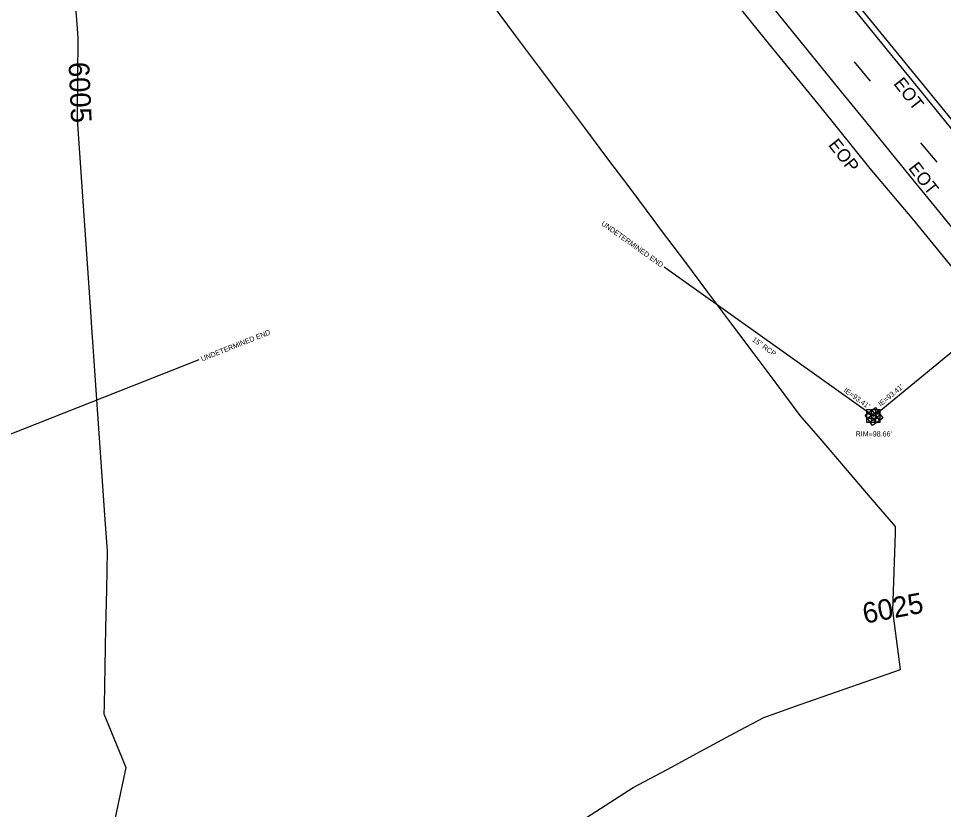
# Model space of a CAD drawing. Extents: x 2132221 to 2141942, y 535736 to 547298.
# Drawn here: x 2137234.9 to 2137595.1, y 540935.8 to 541243.7 of the extents above; entities that cross this region are included whole.
import ezdxf

# ---------------------------------------------------------------- set-up
doc = ezdxf.new("R2010")
doc.units = 0
for name, color, linetype in [('RD_EX_DR_Inlet', 7, 'Continuous'), ('RD_EX_DR_Inlet_txCode', 7, 'Continuous'), ('RD_EX_DR_Pipe', 7, 'Continuous'), ('RD_EX_DR_Pipe_txCode', 7, 'Continuous'), ('RD_EX_Misc', 7, 'Continuous'), ('RD_EX_Misc_txCode', 7, 'Continuous'), ('RD_EX_Road', 7, 'Continuous'), ('RD_EX_Road_txCode', 7, 'Continuous'), ('RD_EX_VEG', 7, 'Continuous'), ('RD_HC_TX_Sta50', 7, 'Continuous')]:
    doc.layers.add(name, color=color, linetype=linetype)

msp = doc.modelspace()

# ---------------------------------------------------------------- linework, layer by layer
at = {"layer": 'RD_EX_DR_Inlet'}
for p, q in [((2137569.6, 541090.81), (2137565.52, 541087.91)), ((2137566.95, 541091.43), (2137566.95, 541086.43)), ((2137567.23, 541091.21), (2137570.13, 541087.14)), ((2137568.65, 541091.43), (2137568.65, 541086.43)), ((2137565.25, 541089.73), (2137570.25, 541089.73)), ((2137565.25, 541088.03), (2137570.25, 541088.03)), ((2137565.84, 541090.23), (2137568.74, 541086.15)), ((2137570.58, 541089.43), (2137566.51, 541086.53))]:
    msp.add_line(p, q, dxfattribs=at)
for points in [[(2137564.54, 541089.3), (2137568.61, 541092.2), (2137571.51, 541088.12), (2137567.44, 541085.22)], [(2137565.25, 541086.43), (2137565.25, 541091.43), (2137570.25, 541091.43), (2137570.25, 541086.43)]]:
    msp.add_lwpolyline(points, close=True, dxfattribs=at)
at = {"layer": 'RD_EX_DR_Pipe'}
for p, q in [((2137567.79, 541088.87), (2137663.53, 541167.56)), ((2137567.79, 541088.87), (2137486.33, 541146.92)), ((2137103.49, 541031.08), (2137305.29, 541110.96))]:
    msp.add_line(p, q, dxfattribs=at)
at = {"layer": 'RD_EX_Misc'}
for p, q in [((2137560.26, 541226.82), (2137566.56, 541219.29)), ((2137586.15, 541195.28), (2137592.45, 541187.76))]:
    msp.add_line(p, q, dxfattribs=at)
for points in [[(2137554.23, 541254.65), (2137563.7, 541243.01), (2137573.16, 541231.38), (2137582.62, 541219.74), (2137592.09, 541208.1), (2137601.55, 541196.47)], [(2137526.86, 541250.09), (2137536.32, 541238.45), (2137545.78, 541226.81), (2137555.25, 541215.18), (2137564.71, 541203.54), (2137574.18, 541191.9), (2137583.64, 541180.26), (2137593.1, 541168.63), (2137602.57, 541156.99)]]:
    msp.add_lwpolyline(points, dxfattribs=at)
at = {"layer": 'RD_EX_Road'}
for points in [[(2137129.75, 541780.57), (2137152.42, 541752.13), (2137176.05, 541723.37), (2137199.18, 541694.95), (2137221.19, 541667.61), (2137243.48, 541640.3), (2137267.28, 541610.96), (2137291.46, 541581.15), (2137312.24, 541555.53), (2137336.72, 541525.3), (2137359.73, 541497.32), (2137378.4, 541474.19), (2137407.74, 541438.19), (2137425.75, 541416.17), (2137446.57, 541390.46), (2137472.54, 541358.27), (2137492.89, 541333.37), (2137514.29, 541307.17), (2137539.52, 541276.53), (2137564.39, 541245.78), (2137586.4, 541218.72), (2137608.31, 541191.93)], [(2137503.28, 541263.26), (2137525.6, 541235.47), (2137547.28, 541208.98), (2137566.43, 541185.33), (2137582.75, 541165.94)], [(2137582.75, 541165.94), (2137604.28, 541139.57), (2137634.31, 541102.54), (2137665.62, 541063.89), (2137693.36, 541029.71), (2137721.58, 540994.92), (2137743.66, 540967.84), (2137762.64, 540943.97), (2137785.25, 540916.82), (2137799.37, 540899.43), (2137792.62, 540897.56), (2137777.51, 540904.78)]]:
    msp.add_lwpolyline(points, dxfattribs=at)
at = {"layer": 'RD_EX_VEG'}
for points in [[(2137256.47, 541256.45), (2137257.64, 541241.49), (2137258.06, 541236.1), (2137257.94, 541221.1), (2137257.82, 541206.1), (2137257.8, 541204.34), (2137258.84, 541189.38), (2137259.88, 541174.41), (2137260.91, 541159.45), (2137261.95, 541144.48), (2137262.99, 541129.52), (2137263.41, 541123.37), (2137264.45, 541108.41), (2137265.49, 541093.44), (2137266.52, 541078.48), (2137267.56, 541063.52), (2137268.6, 541048.55), (2137269.44, 541036.42), (2137269.15, 541021.42), (2137268.86, 541006.42), (2137268.57, 540991.43), (2137268.29, 540976.43), (2137268.22, 540972.93), (2137273.91, 540959.05), (2137276.77, 540952.08), (2137273.63, 540937.42), (2137270.48, 540922.75)], [(2137454.33, 540931.5), (2137466.95, 540939.6), (2137474.23, 540944.27), (2137487.45, 540951.36), (2137500.67, 540958.45), (2137513.88, 540965.54), (2137525.16, 540971.59), (2137539.31, 540976.57), (2137553.46, 540981.55), (2137567.61, 540986.53), (2137578.32, 540990.3), (2137576.41, 541005.18), (2137575.38, 541013.28), (2137575.87, 541028.27), (2137576.36, 541043.26), (2137576.45, 541045.88), (2137566.68, 541057.26), (2137556.92, 541068.65), (2137547.15, 541080.04), (2137539.32, 541089.17), (2137530.32, 541101.17), (2137521.33, 541113.17), (2137512.33, 541125.17), (2137503.33, 541137.18), (2137494.33, 541149.18), (2137485.34, 541161.18), (2137482.43, 541165.06), (2137473.43, 541177.06), (2137464.43, 541189.06), (2137455.44, 541201.06), (2137446.44, 541213.07), (2137437.44, 541225.07), (2137428.45, 541237.07), (2137419.45, 541249.07)]]:
    msp.add_lwpolyline(points, dxfattribs=at)

# ---------------------------------------------------------------- texts
at = {"layer": 'RD_EX_DR_Inlet_txCode'}
for s, rotation, p in [('UNDETERMINED END', 324.5239, (2137461.63, 541163.4)), ('UNDETERMINED END', 21.5951, (2137306.43, 541110.15)), ("IE=93.41'", 324.5239, (2137556.03, 541098.48)), ("IE=93.41'", 39.4173, (2137570.63, 541092.5))]:
    msp.add_text(s, height=2, rotation=rotation, dxfattribs=at).set_placement(p)
msp.add_text("RIM=98.66'", height=2, dxfattribs=at).set_placement((2137560.88, 541080.95))
at = {"layer": 'RD_EX_DR_Pipe_txCode'}
msp.add_text('15" RCP', height=2, rotation=324.5239, dxfattribs=at).set_placement((2137520.38, 541118.22))
at = {"layer": 'RD_EX_Misc_txCode'}
for p in [(2137575.44, 541218.27), (2137581.18, 541185.34)]:
    msp.add_text('EOT', height=5, rotation=307.7833, dxfattribs=at).set_placement(p)
at = {"layer": 'RD_EX_Road_txCode'}
msp.add_text('EOP', height=5, rotation=308.1095, dxfattribs=at).set_placement((2137550.01, 541194.38))
at = {"layer": 'RD_HC_TX_Sta50'}
for s, rotation, p in [('6005', 272.5407, (2137254.42, 541226.61)), ('6005', 272.5407, (2137254.42, 541226.61)), ('6025', 10.7135, (2137564.4, 541008.04))]:
    msp.add_text(s, height=8, rotation=rotation, dxfattribs=at).set_placement(p)

doc.saveas('drawing.dxf')
